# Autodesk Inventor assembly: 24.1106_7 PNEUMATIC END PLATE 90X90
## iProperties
Created: 2010-07
Part Number: 24.1106_7 PNEUMATIC END PLATE 90X90
Document SubType Name: Assembly
Designer: Administrator
Mass: 378.658 g
Surface Area: 428.356 cm^2
Volume: 132.912 cm^3
Density: 2.84894 g/cm^3
Author: Administrator
